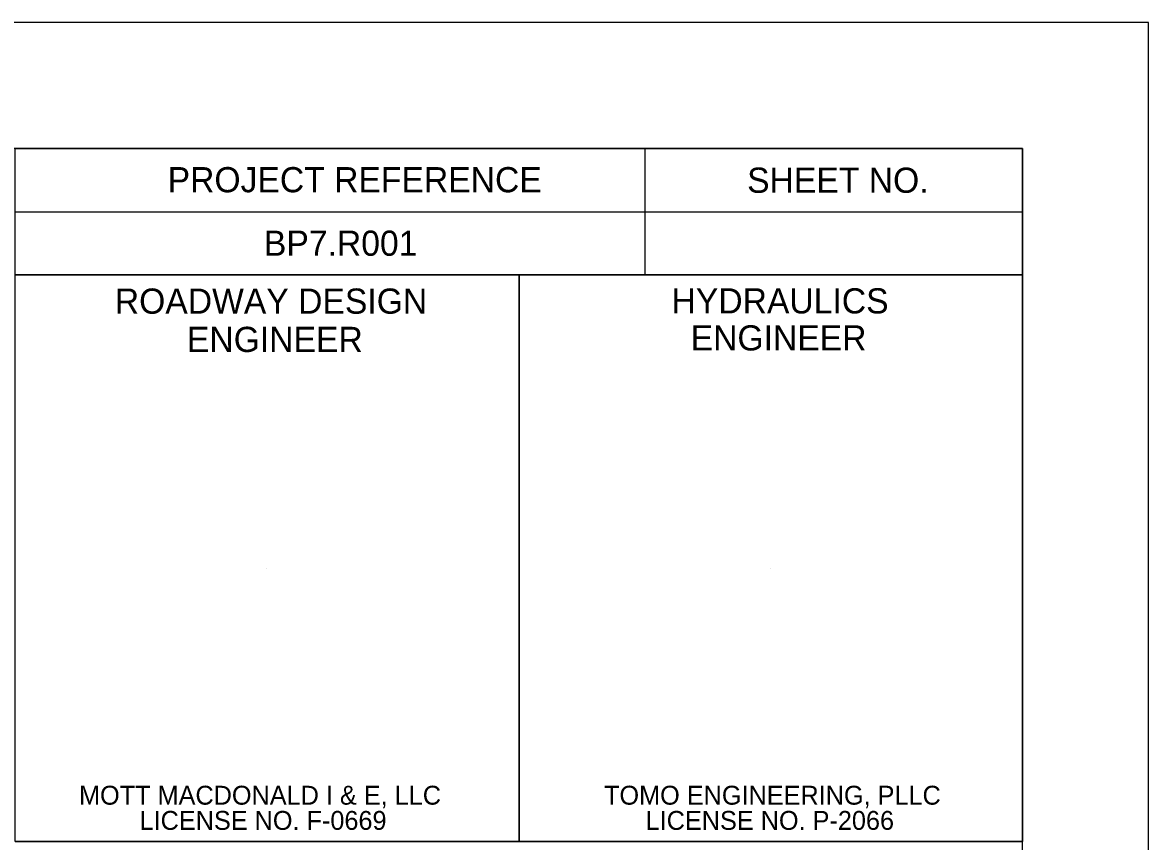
# Model space of a CAD drawing. Extents: x 2474053 to 2475957, y 620456 to 621556.
# Drawn here: x 2475529.3 to 2475752.9, y 621393.6 to 621556.1 of the extents above; entities that cross this region are included whole.
import ezdxf

# ---------------------------------------------------------------- set-up
doc = ezdxf.new("R2010")
doc.units = 0
for name, color, linetype in [('Old_Level_18', 7, 'Continuous'), ('Old_Level_2', 7, 'Continuous'), ('Old_Level_3', 7, 'Continuous'), ('Old_Level_40', 7, 'Continuous'), ('Old_Level_44', 7, 'Continuous'), ('Old_Level_45', 7, 'Continuous'), ('Old_Level_62', 7, 'Continuous'), ('Old_Level_63', 7, 'Continuous'), ('Scratch_Level_3', 7, 'Continuous'), ('Sheet Sticker Exception Certification CELL', 7, 'Continuous')]:
    doc.layers.add(name, color=color, linetype=linetype)

msp = doc.modelspace()

# ---------------------------------------------------------------- linework, layer by layer
at = {"layer": 'Old_Level_18'}
msp.add_lwpolyline([(2475727.88, 621531.13), (2474227.88, 621531.13), (2474227.88, 620481.13), (2475727.88, 620481.13)], close=True, dxfattribs=at)
at = {"layer": 'Old_Level_40'}
for p, q in [((2475652.88, 621531.08), (2475652.88, 621506.08)), ((2475527.83, 621518.58), (2475727.88, 621518.58)), ((2475527.83, 621506.08), (2475727.88, 621506.08)), ((2475527.83, 621506.08), (2475727.88, 621506.08)), ((2475627.88, 621506.08), (2475627.88, 621393.63))]:
    msp.add_line(p, q, dxfattribs=at)
for points in [[(2475527.83, 621531.13), (2475727.88, 621531.13), (2475727.88, 621506.08), (2475527.83, 621506.08)], [(2475527.83, 621506.08), (2475627.88, 621506.08), (2475627.88, 621393.58), (2475527.83, 621393.58)], [(2475627.88, 621506.08), (2475727.88, 621506.08), (2475727.88, 621393.58), (2475627.88, 621393.58)]]:
    msp.add_lwpolyline(points, close=True, dxfattribs=at)
at = {"layer": 'Old_Level_62'}
msp.add_lwpolyline([(2474077.88, 620481.13), (2475727.88, 620481.13), (2475727.88, 621531.13), (2474077.88, 621531.13)], close=True, dxfattribs=at)
at = {"layer": 'Old_Level_63'}
msp.add_lwpolyline([(2474052.88, 620456.13), (2475752.88, 620456.13), (2475752.88, 621556.13), (2474052.88, 621556.13)], close=True, dxfattribs=at)
at = {"layer": 'Scratch_Level_3'}
for p, q in [((2475577.73, 621447.73), (2475577.73, 621447.73)), ((2475677.78, 621447.73), (2475677.78, 621447.73))]:
    msp.add_line(p, q, dxfattribs=at)
at = {"layer": 'Sheet Sticker Exception Certification CELL'}
msp.add_line((2475527.83, 621393.58), (2475727.87, 621393.58), dxfattribs=at)

# ---------------------------------------------------------------- texts
at = {"layer": 'Old_Level_2'}
for s, height, p in [('ROADWAY DESIGN', 5.0001, (2475547.61, 621498.33)), ('ENGINEER', 5, (2475561.93, 621490.73))]:
    msp.add_text(s, height=height, rotation=360, dxfattribs=at).set_placement(p)
at = {"layer": 'Old_Level_3'}
for s, height, p in [('HYDRAULICS', 5, (2475658.17, 621498.38)), ('ENGINEER', 5, (2475661.96, 621491.03)), ('TOMO ENGINEERING, PLLC', 3.75, (2475644.76, 621400.88)), ('LICENSE NO. P-2066', 3.75, (2475653.02, 621395.88))]:
    msp.add_text(s, height=height, rotation=360, dxfattribs=at).set_placement(p)
at = {"layer": 'Old_Level_44'}
for s, height, p in [('PROJECT REFERENCE', 5.0001, (2475558.1, 621522.43)), ('SHEET NO.', 5, (2475673.18, 621522.33)), ('BP7.R001', 5, (2475577.22, 621509.83))]:
    msp.add_text(s, height=height, dxfattribs=at).set_placement(p)
at = {"layer": 'Old_Level_45'}
for s, p in [('MOTT MACDONALD I & E, LLC', (2475540.5, 621400.88)), (' LICENSE NO. F-0669', (2475551.13, 621395.88))]:
    msp.add_text(s, height=3.75, rotation=360, dxfattribs=at).set_placement(p)

doc.saveas('drawing.dxf')
